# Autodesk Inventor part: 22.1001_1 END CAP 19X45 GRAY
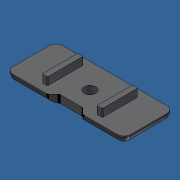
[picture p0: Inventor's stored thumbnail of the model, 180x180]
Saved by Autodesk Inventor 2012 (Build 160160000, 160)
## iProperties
Created: 2013-03
Part Number: 22.1001_1 END CAP 19X45 GRAY
Material: ABS Plastic
Document SubType Name: Modeling
Designer: Admin
Density: 1.06 g/cm^3
Mass: 2.58806 g
Surface Area: 20.9462 cm^2
Volume: 2.44157 cm^3
Author: Admin
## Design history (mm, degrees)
node "11"
sketch "Sketch1"
  geometry: C1 r 2.25 at (0, 0) reference; 1 further point
extrude "Extrusion1" cut sketch "Sketch1" distance "d0" = 10; taper "d1" = 0 deg
node "1"
node "Base1"
